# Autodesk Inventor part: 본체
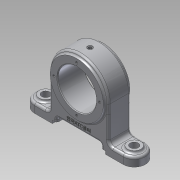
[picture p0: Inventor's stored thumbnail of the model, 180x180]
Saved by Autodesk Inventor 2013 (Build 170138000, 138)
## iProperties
Created: 2019-05
Part Number: 본체
Material: 알루미늄 6061
Document SubType Name: Modeling
Designer: Administrator
Mass: 457.703 g
Surface Area: 318.8 cm^2
Volume: 168.894 cm^3
Density: 2.71 g/cm^3
Author: Administrator
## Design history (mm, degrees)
sketch "스케치12"
  geometry: C1 r 40 at (0, 0); 1 further point
  constraints: 1 centre point, 1 coincident
  dimensions: "d55" = 80 diameter of C1
extrude "돌출9" new body sketch "스케치12" stored distance "d57" = 30; taper "d58" = 0 deg
sketch "스케치13"
  geometry: C1 r 36 at (0, 0); 1 further point
  constraints: 1 centre point, 1 coincident
  dimensions: "d59" = 72 diameter of C1
extrude "돌출10" join sketch "스케치13" stored distance "d61" = 36; taper "d62" = 0 deg
sketch "스케치14"
  geometry: C1 r 36 at (0, 0) reference; C2 r 26 at (0, 0)
  constraints: 1 centre point, 1 coincident
  dimensions: "d63" = 52 diameter of C2
extrude "돌출11" cut sketch "스케치14" stored distance "d65" = 36; taper "d66" = 0 deg
sketch "스케치15"
  geometry: L1 (-40, 0)-(-40, -48); L2 (40, 0)-(40, -48); L3 (-40, -48)-(-75, -48); L4 (-75, -48)-(-75, -60); L5 (-75, -60)-(-36, -60); L6 (-36, -60)-(-36, -56); L7 (-36, -56)-(-30, -56); L8 (-30, -56)-(-30, -50); L9 (-30, -50)-(30, -50); L10 (30, -50)-(30, -56); L11 (30, -56)-(36, -56); L12 (36, -56)-(36, -60); L13 (36, -60)-(75, -60); L14 (75, -60)-(75, -48); L15 (75, -48)-(40, -48); A1 r 40 centre (0, 0) between (-40, 0) and (40, 0) reference; 1 further point
  constraints: 30 end point, 8 vertical, 7 horizontal, 3 collinear, 2 point on circle, 2 tangent
  dimensions: "d67" = 150 distance between parallel lines of L14 L4; "d69" = 12 distance between parallel lines of L3 L5; "d70" = 4 distance between parallel lines of L5 L7; "d71" = 10 distance between parallel lines of L5 L9; "d72" = 36 distance from line of point (0, 0) L6; "d73" = 30 distance from line of point (0, 0) L8; "d74" = 60 distance from line of L5 point (0, 0); "d75" = 60 distance between parallel lines of L10 L8; "d76" = 72 distance between parallel lines of L6 L12; "d77" = 75 distance from line of point (0, 0) L14
extrude "돌출12" join sketch "스케치15" stored distance "d78" = 30; taper "d79" = 0 deg
sketch "스케치16"
  geometry: C1 r 26 at (0, 0) reference; 1 further point
  constraints: 1 vertical alignment
  dimensions: "d80" = 31 distance of C1.centre point (0, 31)
hole "구멍2" sketch "스케치16" at (0, 31) diameter "d81" = 3.242; stored, may be unused: countersink angle "d85" = 90 deg, drill point angle "d87" = 118 deg; dims "d82" = 6, "d83" = 4, "d84" = 2, "d86" = 8
sketch "스케치17"
  geometry: C1 r 1.5 at (0, 26); 1 further point
  constraints: 2 vertical alignment, 1 centre point, 1 other
  dimensions: "d91" = 3 diameter of C1
extrude "돌출13" cut sketch "스케치17" stored distance "d93" = 30; taper "d94" = 0 deg
node "작업 평면3"
sketch "스케치18"
  geometry: C1 r 3.5 at (0, 0); 1 further point
  constraints: 1 centre point, 1 coincident
  dimensions: "d96" = 7 diameter of C1
extrude "돌출14" cut sketch "스케치18" distance "d98" = 1; taper "d99" = 0 deg
sketch "스케치19"
  geometry: C1 r 3.5 at (0, 0) reference; 1 further point
  constraints: 1 coincident
hole "구멍3" sketch "스케치19" at (0, 0) diameter "d100" = 4.917; stored, may be unused: countersink angle "d104" = 90 deg, drill point angle "d106" = 118 deg; dims "d101" = 7, "d102" = 4, "d103" = 2, "d105" = 9
sketch "스케치20"
  geometry: L1 (-30, -50)-(30, -50) reference; C1 r 36 at (0, 0) reference; 1 further point
  constraints: 1 vertical alignment, 1 other
  dimensions: "d107" = 7 distance from line of L1 point (0, -43)
feature "엠보싱1" sketch "스케치20" dims "d108" = 0.5, "d109" = 0
fillet "모깎기1" dims "d110" = 6
sketch "스케치21"
  geometry: C1 r 9 at (15, 15); 1 further point
  constraints: 1 centre point, 1 horizontal alignment
  dimensions: "d111" = 18 diameter of C1; "d113" = 60 distance of point (75, 15) C1.centre
extrude "돌출15" join sketch "스케치21" distance "d114" = 3; taper "d115" = 0 deg
hole "구멍4" diameter "d118" = 11; stored, may be unused: countersink angle "d122" = 90 deg, drill point angle "d124" = 118 deg; dims "d116" = 10, "d117" = 10, "d119" = 8, "d120" = 4, "d121" = 2, "d123" = 10
fillet "모깎기2" dims "d125" = 3
fillet "모깎기4" dims "d127" = 3
fillet "모깎기5" dims "d128" = 15
fillet "모깎기7" dims "d130" = 3
fillet "모깎기6" dims "d129" = 3
chamfer "모따기1" distance "d131" = 1; stored, may be unused: second distance "d132" = 2, angle "d133" = 45 deg
fillet "모깎기8" dims "d136" = 3
hole "구멍5" diameter "d140" = 2; stored, may be unused: countersink angle "d144" = 90 deg, drill point angle "d146" = 118 deg; dims "d138" = 10, "d139" = 10, "d141" = 6, "d142" = 4, "d143" = 2, "d145" = 14
node "솔리드3"
pattern_circular "원형 패턴2" dims angle "d89" = 360 deg
mirror "대칭1"
mirror "대칭2"
